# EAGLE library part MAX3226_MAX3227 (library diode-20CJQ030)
Maxim's MAX3224-MAX3245 ±15kV ESD-Protected, 1?A, 1Mbps, 3.0V to 5.5V, RS-232 Transceivers with AutoShutdown Plus Description: The MAX3224E/MAX3225E/MAX3226E/MAX3227E/ MAX3244E/MAX3245E are 3V-powered EIA/TIA-232 and V.28/V.24 communications interfaces with automatic shutdown/wakeup features, high data-rate capabilities, and enhanced electrostatic discharge (ESD) protection. All transmitter outputs and receiver inputs are protected to ±15kV using IEC 1000-4-2 Air-Gap Discharge, ±8kV using IEC 1000-4-2 Contact Discharge, and ±15kV using the Human Body Model. All devices achieve a 1µA supply current using Maxim's revolutionary AutoShutdown Plus feature. These devices automatically enter a low-power shutdown mode when the RS-232 cable is disconnected or the transmitters of the connected peripherals are inactive, and the UART driving the transmitter inputs is inactive for more than 30 seconds. They turn on again when they sense a valid transition at any transmitter or receiver input. AutoShutdown Plus saves power without hanges to the existing BIOS or operating system. The MAX3225E/MAX3227E/MAX3245E also feature MegaBaud oper ation, guaranteeing 1Mbps for highspeed applications such as communicating with ISDN modems. The MAX3224E/MAX3226E/MAX3244E guarantee 250kbps operation. The transceivers have a proprietary low-dropout transmitter output stage enabling true RS-232 performance from a +3.0V to +5.5V supply with a dual charge pump. The charge pump requires only four small 0.1µF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
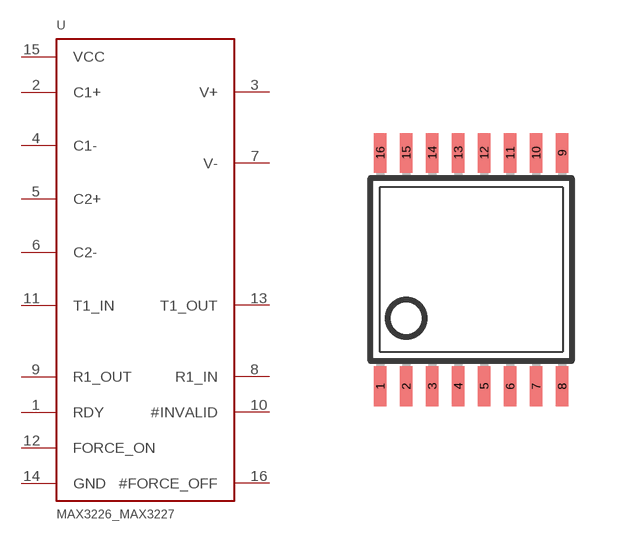
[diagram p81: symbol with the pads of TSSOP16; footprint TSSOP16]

Designator prefix U

## MAX3226_MAX3227  [TSSOP16]
1  RDY  out
2  C1+  in
3  V+  in
4  C1-  in
5  C2+  in
6  C2-  in
7  V-  in
8  R1_IN  in
9  R1_OUT  out
10  #INVALID  out
11  T1_IN  in
12  FORCE_ON  in
13  T1_OUT  in
14  GND  in
15  VCC  in
16  #FORCE_OFF  in

## Footprint TSSOP16 (pad centres in mm)
Thin Shrink Small Outline Plastic 16 MAX3223-MAX3243.pdf
smd 0.305 x 0.991: 1 -2.275,-2.918; 2 -1.625,-2.918; 3 -0.975,-2.918; 4 -0.325,-2.918; 5 0.325,-2.918; 6 0.975,-2.918; 7 1.625,-2.918; 8 2.275,-2.918; 9 2.275,2.918; 10 1.625,2.918; 11 0.975,2.918; 12 0.325,2.918; 13 -0.325,2.918; 14 -0.975,2.918; 15 -1.625,2.918; 16 -2.275,2.918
